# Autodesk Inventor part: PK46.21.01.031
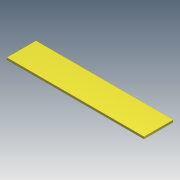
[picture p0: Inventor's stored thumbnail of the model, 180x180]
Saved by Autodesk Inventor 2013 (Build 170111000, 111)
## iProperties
Created: 2005-04
Part Number: PK46.21.01.031
Material: Steel, Mild
Document SubType Name: Modeling
Designer: salex
Manufacturer: Standard
Standards Organization: Custom
Density: 7.86 g/cm^3
Author: salex
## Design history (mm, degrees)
sketch "Эскиз1"
  geometry: L1 (0, 0)-(615, 0); L2 (615, 0)-(615, 130); L3 (615, 130)-(0, 130); L4 (0, 130)-(0, 0)
  constraints: 8 end point, 2 parallel, 1 horizontal, 1 perpendicular, 1 other
  dimensions: "d0" = 130 distance of L3.end L1.start; "d1" = 615 distance of L1.start L1.end
extrude "Выдавливание1" new body sketch "Эскиз1" distance "d2" = 10; taper "d3" = 0 deg
body "Solid1"
